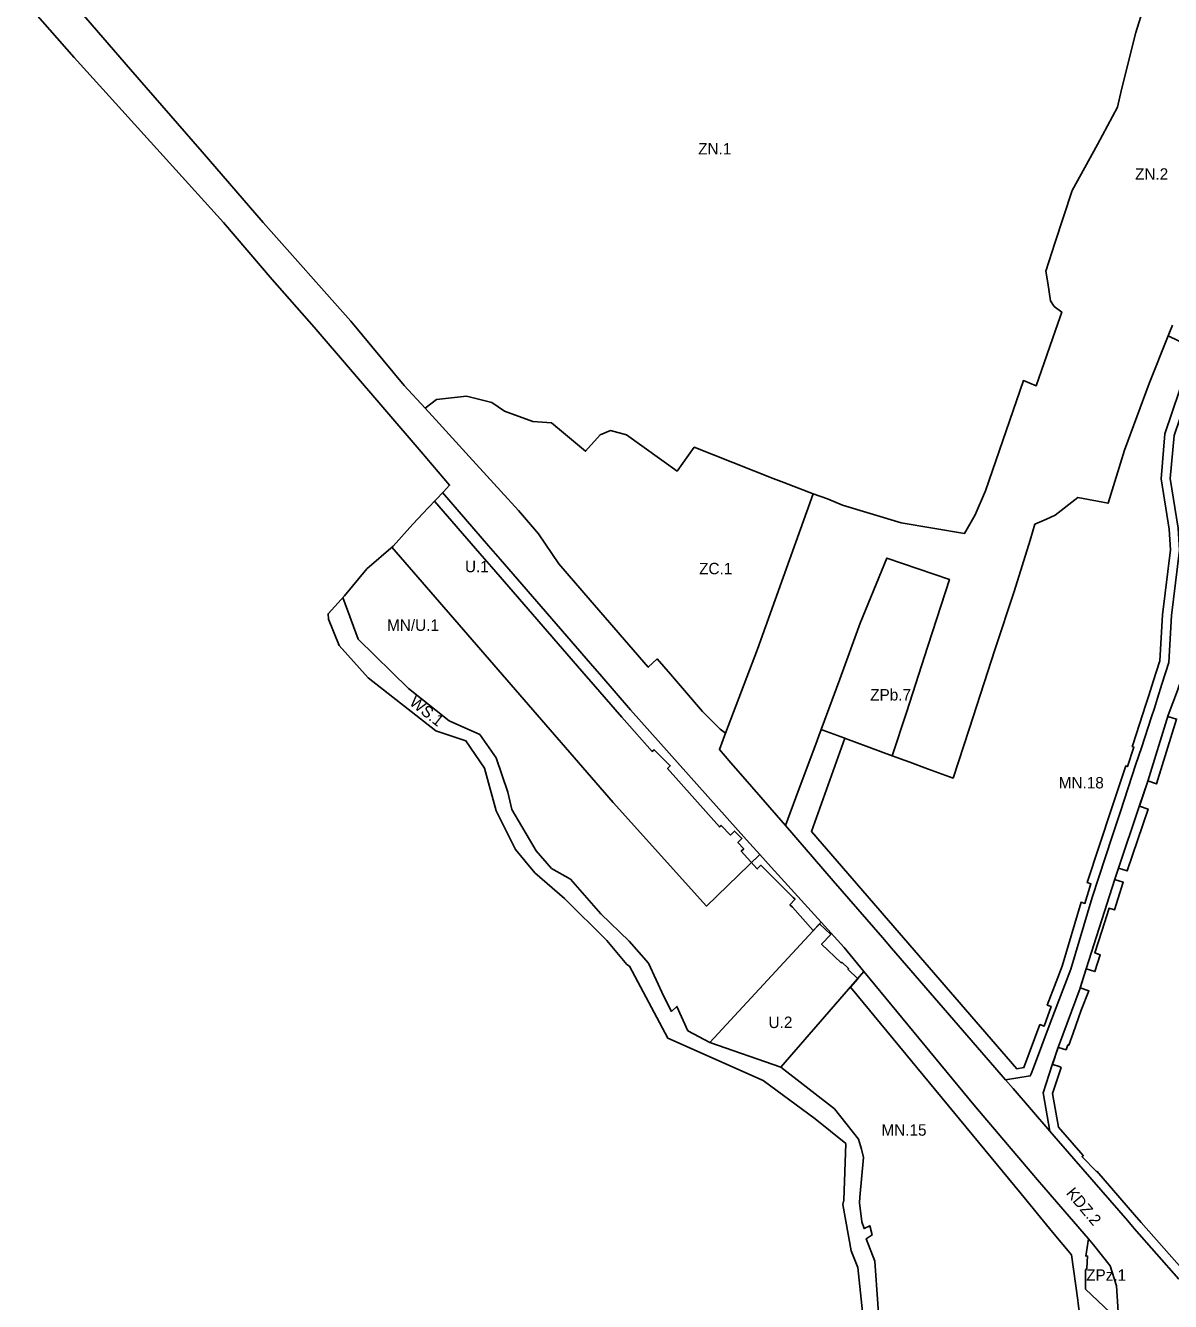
# Model space of a CAD drawing. Extents: x 7416797 to 7419013, y 5549660 to 5551534.
# Drawn here: x 7416862 to 7417362, y 5550440 to 5550998 of the extents above; entities that cross this region are included whole.
import ezdxf

# ---------------------------------------------------------------- set-up
doc = ezdxf.new("R2010")
doc.units = 0
for name, color, linetype in [('LIN_Linia Zabudowy Nieprzekraczalna', 7, 'Continuous'), ('LIN_linie_rozgraniczajace', 7, 'Continuous'), ('TXT_Oznaczenia_przeznaczen', 7, 'Continuous')]:
    doc.layers.add(name, color=color, linetype=linetype)

msp = doc.modelspace()

# ---------------------------------------------------------------- linework, layer by layer
at = {"layer": 'LIN_Linia Zabudowy Nieprzekraczalna'}
for points in [[(7417220.05, 5550686.22), (7417205.46, 5550645.5), (7417295.17, 5550541.92), (7417298.33, 5550542.41), (7417305.27, 5550561.23), (7417307.19, 5550560.56), (7417310.18, 5550569.15), (7417308.52, 5550569.73), (7417312.37, 5550579.91), (7417314.96, 5550586.76), (7417323.27, 5550614.63), (7417324.92, 5550614.11), (7417327.6, 5550622.68), (7417325.99, 5550623.2), (7417336.62, 5550655.47), (7417342.78, 5550674.16), (7417343.53, 5550673.9), (7417346.33, 5550682.4), (7417345.59, 5550682.66), (7417345.81, 5550683.35), (7417350.27, 5550696.86), (7417351.46, 5550700.62), (7417352.82, 5550704.9), (7417354.79, 5550711.09), (7417357.63, 5550720.05), (7417358.76, 5550740.16), (7417362.3, 5550768.58), (7417361.75, 5550777.63), (7417358.21, 5550799.54), (7417359.92, 5550819.22), (7417372.58, 5550856.58)], [(7417222.5, 5550577.57), (7417225.72, 5550581.26), (7417221.41, 5550585.39), (7417221.7, 5550585.71), (7417218.73, 5550588.42), (7417218.51, 5550588.17), (7417209.96, 5550596.36), (7417213.91, 5550600.51), (7417208.98, 5550605.17), (7417206.28, 5550602.32), (7417197.19, 5550612.55), (7417196.09, 5550613.57), (7417198.36, 5550615.95), (7417197.55, 5550616.75), (7417194.38, 5550619.96), (7417183.42, 5550630.76), (7417181.85, 5550629.22), (7417174.85, 5550636.95), (7417175.92, 5550637.98), (7417173.39, 5550640.79), (7417175.16, 5550642.45), (7417171.97, 5550645.74), (7417170.21, 5550643.99), (7417166.03, 5550648.19), (7417165.38, 5550647.56), (7417142.67, 5550673.03), (7417143.85, 5550674.21), (7417136.75, 5550681.23), (7417136.01, 5550680.5), (7417122.7, 5550695.43), (7417110.18, 5550709.89), (7417105.22, 5550715.61), (7417073.34, 5550752.42), (7417065.76, 5550761.17), (7417060.7, 5550767.01), (7417040.91, 5550789.86)], [(7417365.35, 5550707.16), (7417361.36, 5550696.33), (7417361.18, 5550695.75), (7417361.58, 5550695.63), (7417365.01, 5550694.6), (7417356.26, 5550666.29), (7417352.48, 5550667.6), (7417352.46, 5550667.53), (7417348.72, 5550656.6), (7417352.51, 5550655.33), (7417343.42, 5550628.3), (7417339.6, 5550629.5), (7417337.95, 5550624.72), (7417337.91, 5550624.59), (7417337.91, 5550624.59), (7417337.92, 5550624.59), (7417341.71, 5550623.34), (7417337.87, 5550611.25), (7417335.47, 5550612), (7417332.28, 5550602.04), (7417329.26, 5550592.51), (7417331.62, 5550591.62), (7417329.31, 5550584.35), (7417325.53, 5550585.58), (7417325.51, 5550585.59), (7417322.88, 5550577.23), (7417326.68, 5550575.95), (7417323.34, 5550567.53), (7417319.86, 5550557.52), (7417317.85, 5550552.21), (7417317.49, 5550552.34), (7417316.71, 5550550.19), (7417313.41, 5550551.27), (7417313.26, 5550551.32), (7417310.77, 5550543.81), (7417310.89, 5550543.77), (7417313.67, 5550542.83), (7417314.56, 5550542.53), (7417310.78, 5550531.11), (7417313.43, 5550516.44), (7417323.12, 5550505.26), (7417324.21, 5550504), (7417323.68, 5550503.51), (7417330.01, 5550497.01), (7417330.13, 5550497.16), (7417346.65, 5550478.09), (7417349.45, 5550474.83), (7417371.77, 5550449.57)], [(7417247.75, 5550407.37), (7417253.8, 5550408.44), (7417261.96, 5550409.76), (7417304.01, 5550417.81), (7417312.68, 5550419.07), (7417322.33, 5550420.71), (7417324.39, 5550421.04), (7417323.56, 5550427.64), (7417321.99, 5550439.43), (7417321.8, 5550440.84), (7417319.15, 5550460.7), (7417310.86, 5550470.5), (7417297.14, 5550487.32), (7417222.5, 5550577.57)]]:
    msp.add_lwpolyline(points, dxfattribs=at)
at = {"layer": 'LIN_linie_rozgraniczajace'}
for p, q in [((7417161.15, 5550553.44), (7417209.7, 5550605.97)), ((7417192.07, 5550542.59), (7417228.43, 5550584.38))]:
    msp.add_line(p, q, dxfattribs=at)
for points in [[(7417206.22, 5550793.06), (7417212.52, 5550790.81), (7417219.08, 5550788.08), (7417244.62, 5550780.34), (7417272.41, 5550775.72), (7417276.98, 5550783.84), (7417281.51, 5550794.25), (7417298.07, 5550842.46), (7417303.67, 5550840.18), (7417313.15, 5550867.43), (7417314.86, 5550872.36), (7417311.52, 5550874.78), (7417309.85, 5550877.24), (7417308.69, 5550885.21), (7417307.94, 5550890.29), (7417311.77, 5550902.42), (7417319.44, 5550925.43), (7417330.38, 5550945.56), (7417339.21, 5550961.84), (7417340.92, 5550969.54), (7417347.12, 5550994.54), (7417353.32, 5551014.33), (7417357.98, 5551035.17), (7417363.48, 5551053.64)], [(7416873.8, 5551048.57), (7416876.36, 5551021.93), (7416887.43, 5551009.33), (7416883.93, 5551006.26), (7416908.15, 5550978.29), (7416939.33, 5550942.29), (7416965.99, 5550911.51), (7417004.36, 5550868.43), (7417027.66, 5550840.3), (7417036.82, 5550830.38)], [(7417229.81, 5550416.47), (7417225.79, 5550455.14), (7417222.79, 5550462.42), (7417219.22, 5550482.59), (7417219.64, 5550484.56), (7417220.54, 5550509.27), (7417207.09, 5550520.08), (7417184.35, 5550536.72), (7417142.81, 5550555.25), (7417125.97, 5550586.74), (7417124.84, 5550587.5), (7417116.16, 5550597.9), (7417097.6, 5550616.32), (7417084.69, 5550627.5), (7417076.32, 5550637.72), (7417067.88, 5550654.49), (7417062.67, 5550673.14), (7417054.63, 5550685.18), (7417041.39, 5550689.49), (7417011.93, 5550712.67), (7416999.3, 5550726.82), (7416994.58, 5550738.33), (7416994.43, 5550740.66), (7417001.54, 5550748.49), (7417011.35, 5550760.17), (7417022.82, 5550770.2), (7417031.37, 5550779.78), (7417038.15, 5550786.94), (7417044.74, 5550793.91), (7417047.46, 5550796.78), (7417034.98, 5550811.34), (7416988.3, 5550865.78), (7416970.04, 5550886.64), (7416948.79, 5550911.43), (7416883.45, 5550983.52), (7416862.25, 5551007.73)], [(7417363.18, 5550866.69), (7417361.33, 5550862.03)], [(7417361.33, 5550862.03), (7417353.04, 5550841.22), (7417342.24, 5550812.13), (7417335.09, 5550788.88), (7417321.84, 5550791.41), (7417312.02, 5550783.7), (7417308.12, 5550781.95), (7417303.1, 5550779.7), (7417300.98, 5550772.75), (7417294.06, 5550750.34), (7417285.77, 5550725.25), (7417274.35, 5550690.21), (7417267.34, 5550668.84), (7417256.23, 5550672.92), (7417248.47, 5550675.77), (7417240.7, 5550678.63)], [(7417376.24, 5550854.92), (7417374.54, 5550855.63), (7417361.33, 5550862.03)], [(7417290.24, 5550537.11), (7417301.06, 5550538.78), (7417301.49, 5550539.72), (7417302.54, 5550542.26), (7417309.74, 5550561.82), (7417316.13, 5550578.54), (7417318.75, 5550585.48), (7417328.05, 5550616.69), (7417336.82, 5550643.32), (7417340.42, 5550654.22), (7417347.23, 5550674.88), (7417349.61, 5550682.1), (7417354.07, 5550695.63), (7417355.27, 5550699.41), (7417356.63, 5550703.69), (7417358.6, 5550709.88), (7417361.6, 5550719.33), (7417362.74, 5550739.8), (7417366.31, 5550768.44), (7417365.73, 5550778.07), (7417362.23, 5550799.69), (7417363.86, 5550818.4), (7417376.24, 5550854.92)], [(7417036.82, 5550830.38), (7417041.8, 5550834.14), (7417054.9, 5550835.63), (7417065.87, 5550832.95), (7417071.38, 5550829.12), (7417083.86, 5550824.62), (7417091.92, 5550824.01), (7417106.89, 5550811.58), (7417113.26, 5550818.81), (7417117.79, 5550820.61), (7417124.76, 5550818.7), (7417124.71, 5550818.79), (7417146.81, 5550802.92), (7417154.35, 5550813.33), (7417162.8, 5550810), (7417188.85, 5550799.74), (7417193.51, 5550798), (7417206.22, 5550793.06)], [(7417168.01, 5550688.45), (7417165.67, 5550690.21), (7417157.93, 5550697.94), (7417143.91, 5550714.26), (7417138.1, 5550720.91), (7417134.25, 5550717.23), (7417108.82, 5550746.59), (7417095.16, 5550762.36), (7417086.29, 5550775.46), (7417077.56, 5550785.69), (7417056.05, 5550809.35), (7417042.96, 5550823.73), (7417036.82, 5550830.38)], [(7417182.9, 5550635.51), (7417177.17, 5550641.85), (7417126.46, 5550698.73), (7417113.96, 5550713.16), (7417109, 5550718.89), (7417077.12, 5550755.7), (7417069.54, 5550764.45), (7417064.48, 5550770.28), (7417044.37, 5550793.52)], [(7417168.01, 5550688.45), (7417181.91, 5550725.11), (7417193.21, 5550756.43), (7417206.22, 5550793.06)], [(7417022.25, 5550769.7), (7417118.85, 5550658.15), (7417159.73, 5550612.97), (7417182.9, 5550635.51)], [(7417240.7, 5550678.63), (7417247, 5550697.44), (7417256.35, 5550726.4), (7417262.11, 5550744.33), (7417265.78, 5550755.59), (7417238.37, 5550764.97), (7417226.83, 5550736.5), (7417217.84, 5550712.07), (7417209.72, 5550690.02)], [(7417000.88, 5550747.76), (7417007.54, 5550729.55), (7417029.59, 5550707.93), (7417047.22, 5550693.93), (7417060.62, 5550687.87), (7417067.79, 5550677.66), (7417072.95, 5550662.65), (7417074.71, 5550655.12), (7417085.3, 5550637.08), (7417092.02, 5550629.4), (7417100.26, 5550624.73), (7417113.59, 5550609.61), (7417125.83, 5550597.7), (7417134.38, 5550588.04), (7417140.97, 5550573.54), (7417144.39, 5550566.97), (7417146.77, 5550569.14), (7417151.59, 5550558.54), (7417161.15, 5550553.44)], [(7417309.69, 5550514.65), (7417306.66, 5550531.4), (7417310.71, 5550543.64), (7417313.36, 5550551.62), (7417322.85, 5550577.13), (7417325.52, 5550585.62), (7417337.95, 5550624.72), (7417339.62, 5550629.56), (7417348.68, 5550656.48), (7417352.46, 5550667.53), (7417361.36, 5550696.33), (7417365.35, 5550707.16), (7417368.91, 5550717.24), (7417378.45, 5550723.51), (7417382.08, 5550727.09)], [(7417194.13, 5550648.08), (7417175.54, 5550669.55), (7417170.35, 5550675.55), (7417165.32, 5550681.35), (7417168.01, 5550688.45)], [(7417194.13, 5550648.08), (7417199.73, 5550663.12), (7417207.39, 5550683.69), (7417208.72, 5550687.3), (7417209.72, 5550690.02)], [(7417240.7, 5550678.63), (7417220.43, 5550686.08), (7417220.05, 5550686.22), (7417210.42, 5550689.75), (7417209.72, 5550690.02)], [(7417194.13, 5550648.08), (7417215.05, 5550623.93), (7417236.48, 5550599.18), (7417240.41, 5550594.65), (7417290.24, 5550537.11)], [(7417209.7, 5550605.97), (7417187.94, 5550629.94), (7417182.9, 5550635.51)], [(7417228.43, 5550584.38), (7417219.74, 5550594.91), (7417209.7, 5550605.97)], [(7417326.46, 5550467.59), (7417318.07, 5550477.39), (7417304.27, 5550493.41), (7417301.69, 5550496.39), (7417276.43, 5550526.23), (7417228.43, 5550584.38)], [(7417161.15, 5550553.44), (7417192.07, 5550542.59)], [(7417192.07, 5550542.59), (7417215.52, 5550524.38), (7417226.02, 5550511.19), (7417227.34, 5550506.79), (7417228.19, 5550503.17), (7417226.59, 5550485.84), (7417226.54, 5550483.39), (7417227.53, 5550475.07), (7417228.5, 5550472.11), (7417230.95, 5550473.36), (7417232.07, 5550469.35), (7417229.43, 5550467.65), (7417233.13, 5550457.84), (7417235.85, 5550420.62), (7417239.29, 5550395.46)], [(7417309.69, 5550514.65), (7417293.55, 5550533.29), (7417290.24, 5550537.11)], [(7417309.69, 5550514.65), (7417320.09, 5550502.64), (7417343.62, 5550475.48), (7417346.44, 5550472.2), (7417366.03, 5550450.02)], [(7417326.46, 5550467.59), (7417325.31, 5550460.13), (7417326.01, 5550460.16), (7417325.83, 5550454.74), (7417325.27, 5550453.92), (7417325.23, 5550445.71), (7417335.92, 5550435.5), (7417328.63, 5550427.84), (7417332.42, 5550424.03)], [(7417326.46, 5550467.59), (7417328.63, 5550465.05), (7417335.93, 5550455.83), (7417338.71, 5550447.06), (7417339.72, 5550431.23)]]:
    msp.add_lwpolyline(points, dxfattribs=at)

# ---------------------------------------------------------------- texts
at = {"layer": 'TXT_Oznaczenia_przeznaczen'}
for s, p in [('ZN.1', (7417156.05, 5550941.19)), ('ZN.2', (7417346.83, 5550930.17)), ('U.1', (7417054.19, 5550758.74)), ('ZC.1', (7417156.45, 5550757.85)), ('MN/U.1', (7417020.16, 5550733.13)), ('ZPb.7', (7417231.17, 5550702.74)), ('MN.18', (7417313.49, 5550664.32)), ('U.2', (7417186.77, 5550559.69)), ('MN.15', (7417236.07, 5550512.68)), ('ZPz.1', (7417325.49, 5550449.33))]:
    msp.add_text(s, height=5, dxfattribs=at).set_placement(p)
for s, rotation, p in [('WS.1', 321.566, (7417029.52, 5550701.21)), ('KDZ.2', 310.0812, (7417316.47, 5550487.47))]:
    msp.add_text(s, height=5, rotation=rotation, dxfattribs=at).set_placement(p)

doc.saveas('drawing.dxf')
